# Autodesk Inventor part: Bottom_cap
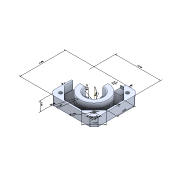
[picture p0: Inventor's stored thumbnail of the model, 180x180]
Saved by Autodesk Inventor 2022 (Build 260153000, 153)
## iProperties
Created: 2020-10
Part Number: Bottom_cap
Material: Generico
Document SubType Name: Modeling
Designer: admin
Density: 1 g/cm^3
Appearance: Default
Sending System: SolidWorks 2020
Last Author: Simon
Last Saved: 2020-10-31
Author: admin
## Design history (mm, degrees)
node "Annotazioni"
  node "Quota lineare 2" dims "d5" = 42 (derived), "d54" = 15
  node "Quota lineare 3" dims "d8" = 42 (derived), "d54" = 15
  node "Quota lineare 4" dims "d11" = 16.07149 (derived), "d54" = 15
  node "Quota lineare 5" dims "d14" = 16.07149 (derived), "d54" = 15
  node "Quota radiale 1" dims "d16" = 13 (derived), "d54" = 15
  node "Quota radiale 2" dims "d18" = 8 (derived), "d54" = 15
  node "Quota lineare 6" dims "d21" = 5.5 (derived), "d54" = 15
  node "Quota lineare 7" dims "d24" = 5.5 (derived), "d54" = 15
  node "Quota diametro 1" dims "d26" = 3 (derived), "d54" = 15
  node "Quota lineare 8" dims "d29" = 1.5 (derived), "d54" = 15
  node "Quota lineare 10" dims "d35" = 9 (derived), "d54" = 15
  node "Quota lineare 11" dims "d38" = 2 (derived), "d54" = 15
  node "Quota diametro 2" dims "d40" = 12 (derived), "d54" = 15
  node "Quota diametro 3" dims "d42" = 9 (derived), "d54" = 15
  node "Quota lineare 12" dims "d45" = 3.99939 (derived), "d54" = 15
  node "Quota lineare 13" dims "d48" = 1 (derived), "d54" = 15
  node "Quota lineare 14" dims "d51" = 0.62772 (derived), "d54" = 15
  node "Quota lineare 15" dims "d54" = 15, "d60" = 2.5 (derived)
  node "Quota lineare 16" dims "d54" = 15, "d63" = 1.5 (derived)
fillet "Fillet7"
node "Asse di lavoro1"
node "Asse di lavoro2"
feature "Filettatura1" dims "d52" = 15, "d53" = 0
feature "Filettatura2" dims "d54" = 15, "d55" = 0
feature "Filettatura3" dims "d56" = 15, "d57" = 0
node "Solido1"
other parameters: "d12" = 0 (derived), "d15" = 14.61797 (derived), "d17" = 12.87277 (derived), "d19" = 8.92075 (derived), "d20" = 0.83591 (derived), "d22" = 0.62622 (derived), "d23" = 0.15516 (derived), "d25" = 18.64797 (derived), "d27" = 5.0804 (derived), "d28" = 5.20268 (derived), "d3" = 2.98413 (derived), "d33" = 7.81774 (derived), "d34" = 0.54901 (derived), "d36" = 5.17941 (derived), "d37" = 0.83579 (derived), "d39" = 60.14052 (derived), "d4" = 5.26559 (derived), "d41" = 52.3533 (derived), "d43" = 6.69281 (derived), "d44" = 4.1142 (derived), "d46" = 6.86803 (derived), "d47" = 7.37418 (derived), "d49" = 3.74854 (derived), "d50" = 5.23199 (derived), "d58" = 5.33035 (derived), "d59" = 9.57753 (derived), "d6" = 7.23224 (derived), "d61" = 2.98894 (derived), "d62" = 8.79192 (derived), "d7" = 5.66851 (derived), "d9" = 0 (derived)
